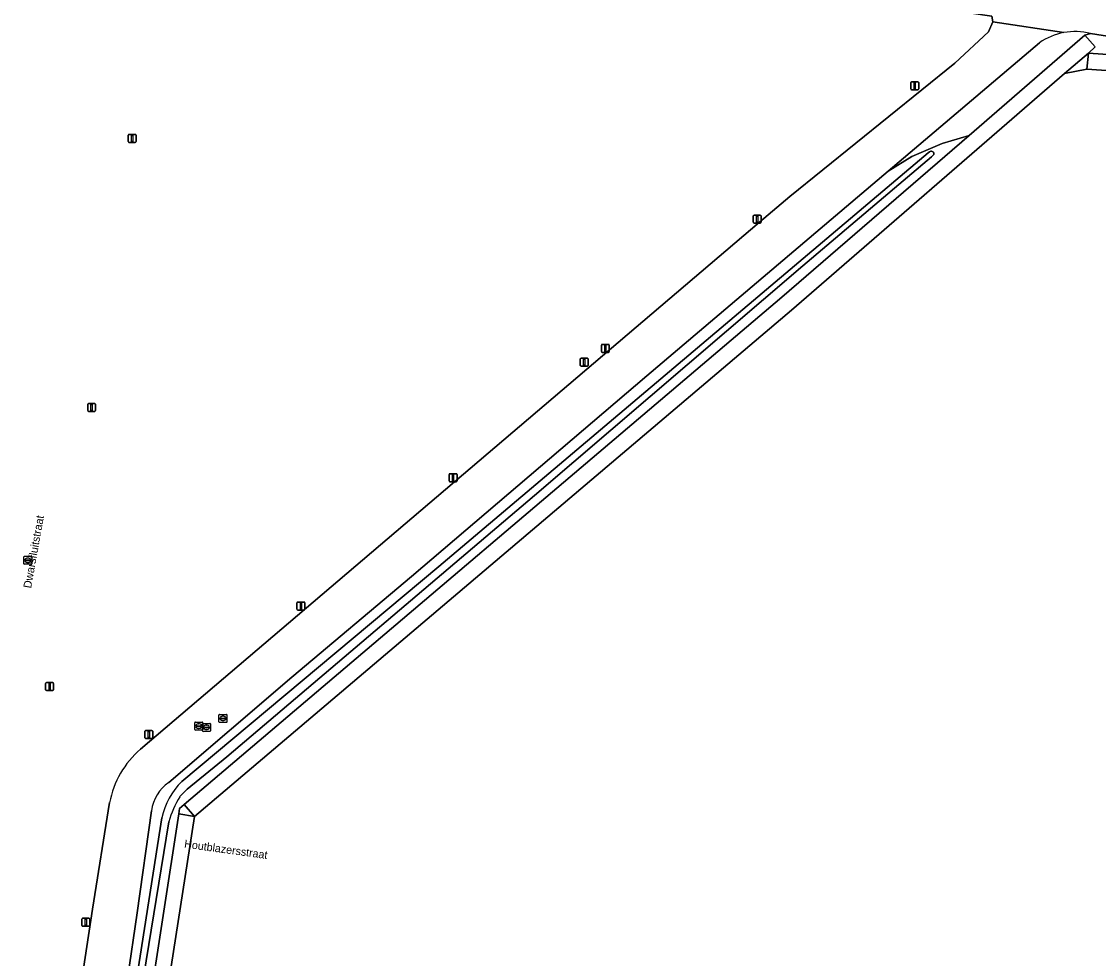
# Model space of a CAD drawing. Extents: x 164148 to 165261, y 382513 to 383432.
# Drawn here: x 164632.6 to 164767.2, y 382690.7 to 382807.8 of the extents above; entities that cross this region are included whole.
import ezdxf

# ---------------------------------------------------------------- set-up
doc = ezdxf.new("R2010")
doc.units = 0
for name, color, linetype in [('IMGEO_Berm_onverhard', 7, 'Continuous'), ('IMGEO_Groenvoorziening', 7, 'Continuous'), ('IMGEO_Lichtmast', 7, 'Continuous'), ('IMGEO_Openbare_ruimte_label', 7, 'Continuous'), ('IMGEO_Rijbaan_lokaal_gesloten', 7, 'Continuous'), ('IMGEO_Rioolput', 7, 'Continuous'), ('IMGEO_Verkeersbordpaal', 7, 'Continuous'), ('IMGEO_Voetpad_gesloten', 7, 'Continuous'), ('IMGEO_Voetpad_open', 7, 'Continuous'), ('IMGEO_Waterloop', 7, 'Continuous')]:
    doc.layers.add(name, color=color, linetype=linetype)

msp = doc.modelspace()

# ---------------------------------------------------------------- linework, layer by layer
at = {"layer": 'IMGEO_Berm_onverhard'}
for points in [[(164759.83, 382805.1), (164740.91, 382789.05), (164743.89, 382790.91), (164747.68, 382792.53), (164751.04, 382793.54), (164765.5, 382806.04)], [(164765.5, 382806.04), (164766.19, 382806.26)]]:
    msp.add_lwpolyline(points, dxfattribs=at)
for centre, start, end in [((164764.23, 382798.95), 100.3343, 125.6451), ((164764.24, 382798.95), 75.0463, 100.3518)]:
    msp.add_arc(centre, 7.56, start, end, dxfattribs=at)
at = {"layer": 'IMGEO_Groenvoorziening'}
for points in [[(164724.82, 382782.68), (164728.63, 382785.89), (164749.25, 382802.57), (164753.46, 382806.47), (164754.01, 382807.74), (164753.88, 382808.42), (164674.76, 382819.95)], [(164778.64, 382800.94), (164765.76, 382801.81), (164762.96, 382801.26), (164728.82, 382771.68), (164654.22, 382708.44), (164648.4, 382670.93), (164649.38, 382670.81), (164648.87, 382666.86), (164642.86, 382667.71), (164641.95, 382662.95), (164641.24, 382657.75), (164641.42, 382657.33), (164645.63, 382656.79), (164649.47, 382656.23), (164651.89, 382654.51), (164671, 382651.46), (164691.7, 382648.46), (164727.5, 382644.01), (164746.97, 382640.98), (164775.54, 382637.44)], [(164652.26, 382708.77), (164652.33, 382709.42), (164652.95, 382709.95), (164727.64, 382773.31), (164751.04, 382793.54), (164747.68, 382792.53), (164743.89, 382790.91), (164740.91, 382789.05), (164710.77, 382763.5), (164681.33, 382738.43), (164666.37, 382725.82), (164651, 382712.67)], [(164652.65, 382712.81), (164684.77, 382739.65), (164745.93, 382791.37), (164746.08, 382791.48), (164746.24, 382791.56), (164746.35, 382791.56), (164746.57, 382791.45), (164746.63, 382791.36), (164746.64, 382791.31), (164746.61, 382791.16), (164746.5, 382791.01), (164746.34, 382790.86), (164730.26, 382777.25), (164696.7, 382748.53), (164658.27, 382715.89), (164653.31, 382711.86), (164652.39, 382710.91)], [(164647.47, 382716.85), (164724.82, 382782.68)], [(164632.62, 382667.4), (164632.96, 382667.34), (164633.77, 382673.24), (164637.81, 382672.69), (164641.49, 382696.86), (164643.6, 382710.16)], [(164648.86, 382709.15), (164647.07, 382696.38), (164643.43, 382671.64), (164646.46, 382671.2), (164652.26, 382708.77)], [(164651.02, 382707.77), (164646.93, 382682.74), (164646.08, 382677.09), (164645.89, 382676.77), (164645.71, 382676.66), (164645.59, 382676.65), (164645.37, 382676.73), (164645.31, 382676.82), (164645.26, 382676.98), (164645.25, 382677.17), (164650.14, 382708.27)]]:
    msp.add_lwpolyline(points, dxfattribs=at)
msp.add_lwpolyline([(164766.19, 382806.26), (164765.5, 382806.04), (164766.77, 382804.58), (164765.96, 382803.8), (164778.63, 382802.92), (164787.96, 382802.85)], close=True, dxfattribs=at)
for centre, radius, start, end in [((164655.17, 382707.93), 11.78, 130.8172, 169.1213), ((164659.19, 382706.23), 9.28, 134.8187, 167.2995), ((164653.71, 382708.62), 4.88, 123.7828, 173.654), ((164662.73, 382704.52), 12.15, 148.2771, 164.51)]:
    msp.add_arc(centre, radius, start, end, dxfattribs=at)
at = {"layer": 'IMGEO_Lichtmast'}
for p, q in [((164743.74, 382799.33), (164743.74, 382800.13)), ((164743.74, 382800.13), (164743.74, 382799.33)), ((164743.84, 382800.23), (164744.63, 382800.23)), ((164744.63, 382800.23), (164743.84, 382800.23)), ((164744.63, 382799.23), (164743.84, 382799.23)), ((164743.84, 382799.23), (164744.63, 382799.23)), ((164744.73, 382800.13), (164744.73, 382799.33)), ((164744.73, 382799.33), (164744.73, 382800.13)), ((164646.03, 382793.66), (164646.82, 382793.66)), ((164646.82, 382793.66), (164646.03, 382793.66)), ((164645.93, 382792.76), (164645.93, 382793.56)), ((164645.93, 382793.56), (164645.93, 382792.76)), ((164646.82, 382792.66), (164646.03, 382792.66)), ((164646.03, 382792.66), (164646.82, 382792.66)), ((164646.92, 382793.56), (164646.92, 382792.76)), ((164646.92, 382792.76), (164646.92, 382793.56)), ((164724.05, 382782.67), (164724.05, 382783.47)), ((164724.05, 382783.47), (164724.05, 382782.67)), ((164724.15, 382783.57), (164724.94, 382783.57)), ((164724.94, 382783.57), (164724.15, 382783.57)), ((164725.04, 382783.47), (164725.04, 382782.67)), ((164725.04, 382782.67), (164725.04, 382783.47)), ((164724.94, 382782.57), (164724.15, 382782.57)), ((164724.15, 382782.57), (164724.94, 382782.57)), ((164705.07, 382766.52), (164705.07, 382767.32)), ((164705.07, 382767.32), (164705.07, 382766.52)), ((164705.17, 382767.42), (164705.96, 382767.42)), ((164705.96, 382767.42), (164705.17, 382767.42)), ((164706.06, 382767.32), (164706.06, 382766.52)), ((164706.06, 382766.52), (164706.06, 382767.32)), ((164705.96, 382766.42), (164705.17, 382766.42)), ((164705.17, 382766.42), (164705.96, 382766.42)), ((164640.87, 382759.14), (164640.87, 382759.94)), ((164640.87, 382759.94), (164640.87, 382759.14)), ((164640.97, 382760.04), (164641.75, 382760.04)), ((164641.75, 382760.04), (164640.97, 382760.04)), ((164641.85, 382759.94), (164641.85, 382759.14)), ((164641.85, 382759.14), (164641.85, 382759.94)), ((164641.75, 382759.04), (164640.97, 382759.04)), ((164640.97, 382759.04), (164641.75, 382759.04)), ((164686.04, 382750.36), (164686.04, 382751.16)), ((164686.04, 382751.16), (164686.04, 382750.36)), ((164686.14, 382751.26), (164686.93, 382751.26)), ((164686.93, 382751.26), (164686.14, 382751.26)), ((164687.03, 382751.16), (164687.03, 382750.36)), ((164687.03, 382750.36), (164687.03, 382751.16)), ((164686.93, 382750.26), (164686.14, 382750.26)), ((164686.14, 382750.26), (164686.93, 382750.26)), ((164667.03, 382734.32), (164667.03, 382735.12)), ((164667.03, 382735.12), (164667.03, 382734.32)), ((164667.13, 382735.22), (164667.92, 382735.22)), ((164667.92, 382735.22), (164667.13, 382735.22)), ((164668.02, 382735.12), (164668.02, 382734.32)), ((164668.02, 382734.32), (164668.02, 382735.12)), ((164667.92, 382734.22), (164667.13, 382734.22)), ((164667.13, 382734.22), (164667.92, 382734.22)), ((164635.62, 382724.27), (164635.62, 382725.06)), ((164635.62, 382725.06), (164635.62, 382724.27)), ((164635.72, 382725.16), (164636.51, 382725.16)), ((164636.51, 382725.16), (164635.72, 382725.16)), ((164636.61, 382725.06), (164636.61, 382724.27)), ((164636.61, 382724.27), (164636.61, 382725.06)), ((164636.51, 382724.17), (164635.72, 382724.17)), ((164635.72, 382724.17), (164636.51, 382724.17)), ((164648.01, 382718.28), (164648.01, 382719.08)), ((164648.01, 382719.08), (164648.01, 382718.28)), ((164648.11, 382719.18), (164648.9, 382719.18)), ((164648.9, 382719.18), (164648.11, 382719.18)), ((164649, 382719.08), (164649, 382718.28)), ((164649, 382718.28), (164649, 382719.08)), ((164648.9, 382718.18), (164648.11, 382718.18)), ((164648.11, 382718.18), (164648.9, 382718.18)), ((164640.14, 382694.82), (164640.14, 382695.62)), ((164640.14, 382695.62), (164640.14, 382694.82)), ((164640.24, 382695.72), (164641.02, 382695.72)), ((164641.02, 382695.72), (164640.24, 382695.72)), ((164641.12, 382695.62), (164641.12, 382694.82)), ((164641.12, 382694.82), (164641.12, 382695.62)), ((164641.02, 382694.72), (164640.24, 382694.72)), ((164640.24, 382694.72), (164641.02, 382694.72))]:
    msp.add_line(p, q, dxfattribs=at)
for points in [[(164744.16, 382800.1), (164744.31, 382800.1), (164744.31, 382799.35), (164744.16, 382799.35), (164744.16, 382800.1)], [(164646.35, 382793.53), (164646.5, 382793.53), (164646.5, 382792.78), (164646.35, 382792.78), (164646.35, 382793.53)], [(164724.47, 382783.44), (164724.62, 382783.44), (164724.62, 382782.69), (164724.47, 382782.69), (164724.47, 382783.44)], [(164705.49, 382767.29), (164705.64, 382767.29), (164705.64, 382766.54), (164705.49, 382766.54), (164705.49, 382767.29)], [(164641.28, 382759.92), (164641.43, 382759.92), (164641.43, 382759.17), (164641.28, 382759.17), (164641.28, 382759.92)], [(164686.46, 382751.14), (164686.61, 382751.14), (164686.61, 382750.39), (164686.46, 382750.39), (164686.46, 382751.14)], [(164667.45, 382735.09), (164667.6, 382735.09), (164667.6, 382734.34), (164667.45, 382734.34), (164667.45, 382735.09)], [(164636.04, 382725.04), (164636.19, 382725.04), (164636.19, 382724.29), (164636.04, 382724.29), (164636.04, 382725.04)], [(164648.43, 382719.05), (164648.58, 382719.05), (164648.58, 382718.3), (164648.43, 382718.3), (164648.43, 382719.05)], [(164640.55, 382695.6), (164640.71, 382695.6), (164640.71, 382694.85), (164640.55, 382694.85), (164640.55, 382695.6)]]:
    msp.add_lwpolyline(points, dxfattribs=at)
for centre, start, end in [((164743.84, 382800.13), 90, 180), ((164743.84, 382800.13), 90, 180), ((164743.84, 382799.33), 180, 270), ((164743.84, 382799.33), 180, 270), ((164744.63, 382800.13), 0, 90), ((164744.63, 382800.13), 360, 90), ((164744.63, 382799.33), 270, 0), ((164744.63, 382799.33), 270, 0), ((164646.03, 382793.56), 90, 180), ((164646.03, 382793.56), 90, 180), ((164646.82, 382793.56), 0, 90), ((164646.82, 382793.56), 360, 90), ((164646.03, 382792.76), 180, 270), ((164646.03, 382792.76), 180, 270), ((164646.82, 382792.76), 270, 0), ((164646.82, 382792.76), 270, 0), ((164724.15, 382783.47), 90, 180), ((164724.15, 382783.47), 90, 180), ((164724.94, 382783.47), 0, 90), ((164724.94, 382783.47), 360, 90), ((164724.15, 382782.67), 180, 270), ((164724.15, 382782.67), 180, 270), ((164724.94, 382782.67), 270, 0), ((164724.94, 382782.67), 270, 0), ((164705.17, 382767.32), 90, 180), ((164705.17, 382767.32), 90, 180), ((164705.96, 382767.32), 0, 90), ((164705.96, 382767.32), 360, 90), ((164705.17, 382766.52), 180, 270), ((164705.17, 382766.52), 180, 270), ((164705.96, 382766.52), 270, 0), ((164705.96, 382766.52), 270, 0), ((164640.97, 382759.94), 90, 180), ((164640.97, 382759.94), 90, 180), ((164641.75, 382759.94), 0, 90), ((164641.75, 382759.94), 360, 90), ((164640.97, 382759.14), 180, 270), ((164640.97, 382759.14), 180, 270), ((164641.75, 382759.14), 270, 0), ((164641.75, 382759.14), 270, 0), ((164686.14, 382751.16), 90, 180), ((164686.14, 382751.16), 90, 180), ((164686.93, 382751.16), 0, 90), ((164686.93, 382751.16), 360, 90), ((164686.14, 382750.36), 180, 270), ((164686.14, 382750.36), 180, 270), ((164686.93, 382750.36), 270, 0), ((164686.93, 382750.36), 270, 0), ((164667.13, 382735.12), 90, 180), ((164667.13, 382735.12), 90, 180), ((164667.92, 382735.12), 0, 90), ((164667.92, 382735.12), 360, 90), ((164667.13, 382734.32), 180, 270), ((164667.13, 382734.32), 180, 270), ((164667.92, 382734.32), 270, 0), ((164667.92, 382734.32), 270, 0), ((164635.72, 382725.06), 90, 180), ((164635.72, 382725.06), 90, 180), ((164636.51, 382725.06), 0, 90), ((164636.51, 382725.06), 360, 90), ((164635.72, 382724.27), 180, 270), ((164635.72, 382724.27), 180, 270), ((164636.51, 382724.27), 270, 0), ((164636.51, 382724.27), 270, 0), ((164648.11, 382719.08), 90, 180), ((164648.11, 382719.08), 90, 180), ((164648.11, 382718.28), 180, 270), ((164648.11, 382718.28), 180, 270), ((164648.9, 382719.08), 0, 90), ((164648.9, 382719.08), 360, 90), ((164648.9, 382718.28), 270, 0), ((164648.9, 382718.28), 270, 0), ((164640.24, 382695.62), 90, 180), ((164640.24, 382695.62), 90, 180), ((164641.02, 382695.62), 0, 90), ((164641.02, 382695.62), 360, 90), ((164640.24, 382694.82), 180, 270), ((164640.24, 382694.82), 180, 270), ((164641.02, 382694.82), 270, 0), ((164641.02, 382694.82), 270, 0)]:
    msp.add_arc(centre, 0.1, start, end, dxfattribs=at)
at = {"layer": 'IMGEO_Rijbaan_lokaal_gesloten'}
for points in [[(164766.19, 382806.26), (164787.96, 382802.85), (164789.36, 382802.85), (164789.65, 382802.82), (164790.6, 382807.74), (164790.12, 382807.81), (164775.71, 382810.04), (164760.72, 382813.01), (164754.95, 382813.58), (164691.5, 382822.53), (164676.08, 382824.82), (164661.54, 382827.31)], [(164674.76, 382819.95), (164753.88, 382808.42), (164754.01, 382807.74), (164762.88, 382806.39)], [(164762.88, 382806.39), (164754.01, 382807.74), (164753.46, 382806.47), (164749.25, 382802.57), (164728.63, 382785.89), (164724.82, 382782.68), (164647.47, 382716.85)], [(164740.91, 382789.05), (164759.83, 382805.1)], [(164651, 382712.67), (164666.37, 382725.82), (164681.33, 382738.43), (164710.77, 382763.5), (164740.91, 382789.05)], [(164643.6, 382710.16), (164641.49, 382696.86), (164637.81, 382672.69), (164637.43, 382670.27), (164637.16, 382668.38), (164636.98, 382667.13), (164636.49, 382661.87)], [(164633.57, 382658.82), (164632.61, 382658.95), (164633.02, 382651.91), (164640.17, 382650.99), (164641.24, 382657.75), (164641.95, 382662.95), (164642.86, 382667.71), (164643.43, 382671.64), (164647.07, 382696.38), (164648.86, 382709.15)]]:
    msp.add_lwpolyline(points, dxfattribs=at)
for centre, radius, start, end in [((164764.23, 382798.95), 7.56, 100.3343, 125.6451), ((164764.24, 382798.95), 7.56, 75.0463, 100.3518), ((164655.17, 382707.93), 11.78, 130.8172, 169.1213), ((164653.71, 382708.62), 4.88, 123.7828, 173.654)]:
    msp.add_arc(centre, radius, start, end, dxfattribs=at)
at = {"layer": 'IMGEO_Rioolput'}
for p, q in [((164632.89, 382740.01), (164632.89, 382740.86)), ((164632.97, 382740.94), (164633.82, 382740.94)), ((164633.82, 382739.94), (164632.97, 382739.94)), ((164633.15, 382740.43), (164633.15, 382740.44)), ((164633.19, 382740.48), (164633.59, 382740.48)), ((164633.59, 382740.39), (164633.19, 382740.39)), ((164633.38, 382740.72), (164633.4, 382740.72)), ((164633.4, 382740.16), (164633.38, 382740.16)), ((164633.63, 382740.44), (164633.63, 382740.43)), ((164633.89, 382740.86), (164633.89, 382740.01)), ((164657.28, 382720.26), (164657.28, 382721.12)), ((164657.36, 382721.19), (164658.21, 382721.19)), ((164657.77, 382720.97), (164657.79, 382720.97)), ((164658.28, 382721.12), (164658.28, 382720.26)), ((164654.25, 382719.3), (164654.25, 382720.15)), ((164654.33, 382720.22), (164655.18, 382720.22)), ((164654.51, 382719.72), (164654.51, 382719.73)), ((164654.55, 382719.77), (164654.95, 382719.77)), ((164654.95, 382719.68), (164654.55, 382719.68)), ((164654.74, 382720), (164654.76, 382720)), ((164654.99, 382719.73), (164654.99, 382719.72)), ((164655.21, 382719.14), (164655.21, 382719.99)), ((164655.25, 382720.15), (164655.25, 382719.3)), ((164655.28, 382720.07), (164656.14, 382720.07)), ((164655.47, 382719.56), (164655.47, 382719.57)), ((164655.51, 382719.61), (164655.91, 382719.61)), ((164655.7, 382719.85), (164655.72, 382719.85)), ((164655.95, 382719.57), (164655.95, 382719.56)), ((164656.21, 382719.99), (164656.21, 382719.14)), ((164658.21, 382720.19), (164657.36, 382720.19)), ((164657.54, 382720.68), (164657.54, 382720.7)), ((164657.58, 382720.73), (164657.98, 382720.73)), ((164657.98, 382720.65), (164657.58, 382720.65)), ((164657.79, 382720.41), (164657.77, 382720.41)), ((164658.02, 382720.7), (164658.02, 382720.68)), ((164655.18, 382719.22), (164654.33, 382719.22)), ((164654.76, 382719.44), (164654.74, 382719.44)), ((164656.14, 382719.07), (164655.28, 382719.07)), ((164655.91, 382719.52), (164655.51, 382719.52)), ((164655.72, 382719.29), (164655.69, 382719.29))]:
    msp.add_line(p, q, dxfattribs=at)
for points in [[(164632.89, 382740.01), (164632.89, 382740.86)], [(164632.97, 382740.94), (164633.82, 382740.94)], [(164633.82, 382739.94), (164632.97, 382739.94)], [(164633.89, 382740.86), (164633.89, 382740.01)], [(164657.28, 382720.26), (164657.28, 382721.12)], [(164657.36, 382721.19), (164658.21, 382721.19)], [(164658.28, 382721.12), (164658.28, 382720.26)], [(164654.25, 382719.3), (164654.25, 382720.15)], [(164654.33, 382720.22), (164655.18, 382720.22)], [(164655.21, 382719.14), (164655.21, 382719.99)], [(164655.25, 382720.15), (164655.25, 382719.3)], [(164655.28, 382720.07), (164656.14, 382720.07)], [(164656.21, 382719.99), (164656.21, 382719.14)], [(164658.21, 382720.19), (164657.36, 382720.19)], [(164655.18, 382719.22), (164654.33, 382719.22)], [(164656.14, 382719.07), (164655.28, 382719.07)]]:
    msp.add_lwpolyline(points, dxfattribs=at)
for centre, radius, start, end in [((164632.97, 382740.86), 0.0765, 91.552, 178.448), ((164632.97, 382740.86), 0.0765, 91.552, 178.448), ((164632.97, 382740.01), 0.0765, 181.552, 268.448), ((164632.97, 382740.01), 0.0765, 181.552, 268.448), ((164633.19, 382740.44), 0.0403, 85.8775, 175.7526), ((164633.19, 382740.43), 0.0366, 178.938, 274.7102), ((164633.6, 382740.44), 0.0386, 1.7309, 96.639), ((164633.59, 382740.44), 0.043, 264.8664, 352.4533), ((164633.82, 382740.86), 0.0765, 1.552, 88.448), ((164633.82, 382740.86), 0.0765, 1.552, 88.448), ((164633.82, 382740.01), 0.0765, 271.552, 358.448), ((164633.82, 382740.01), 0.0765, 271.552, 358.448), ((164657.36, 382721.11), 0.0765, 91.552, 178.448), ((164657.36, 382721.11), 0.0765, 91.552, 178.448), ((164658.21, 382721.11), 0.0765, 1.552, 88.448), ((164658.21, 382721.11), 0.0765, 1.552, 88.448), ((164654.33, 382720.15), 0.0765, 91.552, 178.448), ((164654.33, 382720.15), 0.0765, 91.552, 178.448), ((164654.55, 382719.73), 0.0403, 85.8775, 175.7526), ((164654.55, 382719.72), 0.0366, 178.938, 274.7102), ((164654.96, 382719.73), 0.0386, 1.7309, 96.639), ((164654.95, 382719.72), 0.043, 264.8664, 352.4533), ((164655.18, 382720.15), 0.0765, 1.552, 88.448), ((164655.18, 382720.15), 0.0765, 1.552, 88.448), ((164655.29, 382719.99), 0.0765, 91.552, 178.448), ((164655.29, 382719.99), 0.0765, 91.552, 178.448), ((164655.51, 382719.57), 0.0403, 85.8775, 175.7526), ((164655.5, 382719.56), 0.0366, 178.938, 274.7102), ((164655.91, 382719.57), 0.0386, 1.7309, 96.639), ((164655.91, 382719.57), 0.043, 264.8664, 352.4533), ((164656.13, 382719.99), 0.0765, 1.552, 88.448), ((164656.13, 382719.99), 0.0765, 1.552, 88.448), ((164657.36, 382720.27), 0.0765, 181.552, 268.448), ((164657.36, 382720.27), 0.0765, 181.552, 268.448), ((164657.58, 382720.69), 0.0403, 85.8775, 175.7526), ((164657.58, 382720.68), 0.0366, 178.938, 274.7102), ((164657.99, 382720.69), 0.0386, 1.7309, 96.639), ((164657.98, 382720.69), 0.043, 264.8664, 352.4533), ((164658.21, 382720.27), 0.0765, 271.552, 358.448), ((164658.21, 382720.27), 0.0765, 271.552, 358.448), ((164654.33, 382719.3), 0.0765, 181.552, 268.448), ((164654.33, 382719.3), 0.0765, 181.552, 268.448), ((164655.18, 382719.3), 0.0765, 271.552, 358.448), ((164655.18, 382719.3), 0.0765, 271.552, 358.448), ((164655.29, 382719.14), 0.0765, 181.552, 268.448), ((164655.29, 382719.14), 0.0765, 181.552, 268.448), ((164656.13, 382719.14), 0.0765, 271.552, 358.448), ((164656.13, 382719.14), 0.0765, 271.552, 358.448)]:
    msp.add_arc(centre, radius, start, end, dxfattribs=at)
for centre, major_axis, ratio, start_param, end_param in [((164633.38, 382740.44), (-0.387, 0.002), 0.722429, 4.712389, 7.853982), ((164633.4, 382740.44), (-0.39, 0.002), 0.717154, 1.570796, 4.712389), ((164657.77, 382720.69), (-0.387, 0.002), 0.722429, 4.712389, 7.853982), ((164657.79, 382720.69), (-0.39, 0.002), 0.717154, 1.570796, 4.712389), ((164654.74, 382719.72), (-0.387, 0.002), 0.722429, 4.712389, 7.853982), ((164654.76, 382719.72), (-0.39, 0.002), 0.717154, 1.570796, 4.712389), ((164655.7, 382719.57), (-0.387, 0.002), 0.722429, 4.712389, 7.853982), ((164655.72, 382719.57), (-0.39, 0.002), 0.717154, 1.570796, 4.712389)]:
    msp.add_ellipse(centre, major_axis=major_axis, ratio=ratio, start_param=start_param, end_param=end_param, dxfattribs=at)
at = {"layer": 'IMGEO_Verkeersbordpaal'}
for p, q in [((164702.44, 382764.8), (164702.44, 382765.6)), ((164702.44, 382765.6), (164702.44, 382764.8)), ((164702.54, 382765.7), (164703.33, 382765.7)), ((164703.33, 382765.7), (164702.54, 382765.7)), ((164703.43, 382765.6), (164703.43, 382764.8)), ((164703.43, 382764.8), (164703.43, 382765.6)), ((164703.33, 382764.7), (164702.54, 382764.7)), ((164702.54, 382764.7), (164703.33, 382764.7))]:
    msp.add_line(p, q, dxfattribs=at)
msp.add_lwpolyline([(164702.86, 382765.58), (164703.01, 382765.58), (164703.01, 382764.83), (164702.86, 382764.83), (164702.86, 382765.58)], dxfattribs=at)
for centre, start, end in [((164702.54, 382765.6), 90, 180), ((164702.54, 382765.6), 90, 180), ((164703.33, 382765.6), 0, 90), ((164703.33, 382765.6), 360, 90), ((164702.54, 382764.8), 180, 270), ((164702.54, 382764.8), 180, 270), ((164703.33, 382764.8), 270, 0), ((164703.33, 382764.8), 270, 0)]:
    msp.add_arc(centre, 0.1, start, end, dxfattribs=at)
at = {"layer": 'IMGEO_Voetpad_gesloten'}
for points in [[(164728.82, 382771.68), (164762.96, 382801.26), (164765.96, 382803.8), (164766.77, 382804.58), (164765.5, 382806.04), (164751.04, 382793.54), (164727.64, 382773.31), (164652.95, 382709.95), (164654.22, 382708.44)], [(164765.76, 382801.81), (164778.64, 382800.94), (164787.78, 382800.87), (164787.9, 382801.04), (164787.96, 382802.85), (164778.63, 382802.92), (164765.96, 382803.8)], [(164643.43, 382671.64), (164642.86, 382667.71), (164648.87, 382666.86), (164649.38, 382670.81), (164648.4, 382670.93), (164654.22, 382708.44), (164652.26, 382708.77), (164646.46, 382671.2)]]:
    msp.add_lwpolyline(points, close=True, dxfattribs=at)
at = {"layer": 'IMGEO_Voetpad_open'}
for points in [[(164765.76, 382801.81), (164765.96, 382803.8), (164762.96, 382801.26)], [(164652.95, 382709.95), (164652.33, 382709.42), (164652.26, 382708.77), (164654.22, 382708.44)]]:
    msp.add_lwpolyline(points, close=True, dxfattribs=at)
at = {"layer": 'IMGEO_Waterloop'}
for points in [[(164746.34, 382790.86), (164746.5, 382791.01), (164746.61, 382791.16), (164746.64, 382791.31), (164746.63, 382791.36), (164746.57, 382791.45), (164746.35, 382791.56), (164746.24, 382791.56), (164746.08, 382791.48), (164745.93, 382791.37), (164684.77, 382739.65), (164652.65, 382712.81)], [(164652.39, 382710.91), (164653.31, 382711.86), (164658.27, 382715.89), (164696.7, 382748.53), (164730.26, 382777.25), (164746.34, 382790.86)], [(164650.14, 382708.27), (164645.25, 382677.17), (164645.26, 382676.98), (164645.31, 382676.82), (164645.37, 382676.73), (164645.59, 382676.65), (164645.71, 382676.66), (164645.89, 382676.77), (164646.08, 382677.09), (164646.93, 382682.74), (164651.02, 382707.77)]]:
    msp.add_lwpolyline(points, dxfattribs=at)
for centre, radius, start, end in [((164659.19, 382706.23), 9.28, 134.8187, 167.2995), ((164662.73, 382704.52), 12.15, 148.2771, 164.51)]:
    msp.add_arc(centre, radius, start, end, dxfattribs=at)

# ---------------------------------------------------------------- texts
at = {"layer": 'IMGEO_Openbare_ruimte_label'}
for s, rotation, p in [('Dwarsfluitstraat', 79.8592, (164633.8, 382736.89)), ('Houtblazersstraat', 352.1291, (164652.89, 382704.55))]:
    msp.add_text(s, height=1, rotation=rotation, dxfattribs=at).set_placement(p)

doc.saveas('drawing.dxf')
